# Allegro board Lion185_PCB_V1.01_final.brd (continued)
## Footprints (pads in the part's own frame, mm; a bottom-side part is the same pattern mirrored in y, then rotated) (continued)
CAE630W570HN
  rect 3.5x1.6 smd: 1(-2.85,0) 2(2.85,0)
CAE660W800HN
  rect 3.35x1.6 smd: 1(-2.45,0) 2(2.45,0)
CC0402N
  rect 0.55x0.5 smd: 1(-0.475,0) 2(0.475,0)
CC0603N
  rect 0.8x0.8 smd: 1(-0.75,0) 2(0.75,0)
CC0805N
  rect 1x1.2 smd: 1(-1,0) 2(1,0)
CC1206N
  rect 1.2x1.6 smd: 1(-1.6,0) 2(1.6,0)
CC1210N
  rect 1.3x2.6 smd: 1(-1.4,0) 2(1.4,0)
CCP7343N
  rect 2.6x2.6 smd: 1(-3.05,0) 2(3.05,0)
DOT
  round 0.508 smd: 1(0,0)
F1206N
  rect 1.3x1.8 smd: 1(-1.45,0) 2(1.45,0)
FB0603N
  rect 0.8x0.8 smd: 1(-0.75,0) 2(0.75,0)
FB0805N
  rect 1x1.2 smd: 1(-1,0) 2(1,0)
FB1206N
  rect 1.2x1.6 smd: 1(-1.6,0) 2(1.6,0)
FIL_175P200X120-4L
  rect 0.6x0.7 smd: 1(-0.5,0.875) 2(-0.5,-0.875) 3(0.5,-0.875) 4(0.5,0.875)
KPAK127P605-9N
  rect 0.9x1.5 smd: (-1.757,1.811)
  rect 0.7x0.5 smd: 1(-2.79,1.905) 3(2.79,-1.905) 4(2.79,-0.635) 5(2.79,0.635) 6(2.79,1.905)
  rect 1.85x3 smd: 2(-2.215,-0.637)
  rect 2.6x4.8 smd: 7(0.47,0.004)
LC3030DL
  rect 1.5x3.2 smd: 1(-1.05,0) 2(1.05,0)
LC4340N
  rect 2.5x1.5 smd: 1(0,1.85) 2(0,-1.85)
LC5757N
  rect 2.15x6.3 smd: 1(-2.075,0) 2(2.075,0)
LC6666N
  rect 2.3x3.3 smd: 1(-3.075,0) 2(3.075,0)
LC7266N
  rect 3.5x2.6 smd: 1(0,3.15) 2(0,-3.15)
LQFP40P1600X1600-128N
  oval 1.3x0.2 smd: 1(-7.65,6.2) 2(-7.65,5.8) 3(-7.65,5.4) 4(-7.65,5) 5(-7.65,4.6) 6(-7.65,4.2) 7(-7.65,3.8) 8(-7.65,3.4) 9(-7.65,3) 10(-7.65,2.6) 11(-7.65,2.2) 12(-7.65,1.8) 13(-7.65,1.4) 14(-7.65,1) 15(-7.65,0.6) 16(-7.65,0.2) 17(-7.65,-0.2) 18(-7.65,-0.6) 19(-7.65,-1) 20(-7.65,-1.4) 21(-7.65,-1.8) 22(-7.65,-2.2) 23(-7.65,-2.6) 24(-7.65,-3) 25(-7.65,-3.4) 26(-7.65,-3.8) 27(-7.65,-4.2) 28(-7.65,-4.6) 29(-7.65,-5) 30(-7.65,-5.4) 31(-7.65,-5.8) 32(-7.65,-6.2) 65(7.65,-6.2) 66(7.65,-5.8) 67(7.65,-5.4) 68(7.65,-5) 69(7.65,-4.6) 70(7.65,-4.2) 71(7.65,-3.8) 72(7.65,-3.4) 73(7.65,-3) 74(7.65,-2.6) 75(7.65,-2.2) 76(7.65,-1.8) 77(7.65,-1.4) 78(7.65,-1) 79(7.65,-0.6) 80(7.65,-0.2) 81(7.65,0.2) 82(7.65,0.6) 83(7.65,1) 84(7.65,1.4) 85(7.65,1.8) 86(7.65,2.2) 87(7.65,2.6) 88(7.65,3) 89(7.65,3.4) 90(7.65,3.8) 91(7.65,4.2) 92(7.65,4.6) 93(7.65,5) 94(7.65,5.4) 95(7.65,5.8) 96(7.65,6.2)
  oval 0.2x1.3 smd: 33(-6.2,-7.65) 34(-5.8,-7.65) 35(-5.4,-7.65) 36(-5,-7.65) 37(-4.6,-7.65) 38(-4.2,-7.65) 39(-3.8,-7.65) 40(-3.4,-7.65) 41(-3,-7.65) 42(-2.6,-7.65) 43(-2.2,-7.65) 44(-1.8,-7.65) 45(-1.4,-7.65) 46(-1,-7.65) 47(-0.6,-7.65) 48(-0.2,-7.65) 49(0.2,-7.65) 50(0.6,-7.65) 51(1,-7.65) 52(1.4,-7.65) 53(1.8,-7.65) 54(2.2,-7.65) 55(2.6,-7.65) 56(3,-7.65) 57(3.4,-7.65) 58(3.8,-7.65) 59(4.2,-7.65) 60(4.6,-7.65) 61(5,-7.65) 62(5.4,-7.65) 63(5.8,-7.65) 64(6.2,-7.65) 97(6.2,7.65) 98(5.8,7.65) 99(5.4,7.65) 100(5,7.65) 101(4.6,7.65) 102(4.2,7.65) 103(3.8,7.65) 104(3.4,7.65) 105(3,7.65) 106(2.6,7.65) 107(2.2,7.65) 108(1.8,7.65) 109(1.4,7.65) 110(1,7.65) 111(0.6,7.65) 112(0.2,7.65) 113(-0.2,7.65) 114(-0.6,7.65) 115(-1,7.65) 116(-1.4,7.65) 117(-1.8,7.65) 118(-2.2,7.65) 119(-2.6,7.65) 120(-3,7.65) 121(-3.4,7.65) 122(-3.8,7.65) 123(-4.2,7.65) 124(-4.6,7.65) 125(-5,7.65) 126(-5.4,7.65) 127(-5.8,7.65) 128(-6.2,7.65)
MARK-D100D250
  round 1 smd: 1(0,0)
MTG340H600
  round 6 hole 3.4: 1(0,0)
MTG340R580
  rect 5.8x5.8 hole 3.4: 1(0,0)
MTG380H500
  round 5 hole 3.8: 1(0,0)
MTG400H600
  round 6 hole 4: 1(0,0)
OSC120P150X670-4L
  rect 0.6x0.9 smd: 1(-0.6,3.3) 2(-0.6,-3.3) 3(0.6,-3.3) 4(0.6,3.3)
OSC127P200X600-2L
  rect 0.6x2.5 smd: 1(-0.6,4.98) 2(0.6,4.98)
OSC170P320X250-4N
  rect 1.4x1.15 smd: 1(-1.1,-0.85) 2(1.1,-0.85) 3(1.1,0.85) 4(-1.1,0.85)
PQFP50P365X365-14N
  oval 0.7x0.28 smd: 1(-1.775,-0.75) 7(1.775,-0.75) 8(1.775,0.75) 14(-1.775,0.75)
  oval 0.28x0.7 smd: 2(-1,-1.775) 3(-0.5,-1.775) 4(0,-1.775) 5(0.5,-1.775) 6(1,-1.775) 9(1,1.775) 10(0.5,1.775) 11(0,1.775) 12(-0.5,1.775) 13(-1,1.775)
  rect 2.05x2.05 smd: E1(0,0)
PVQFN50P480X480-24N
  oval 0.7x0.28 smd: 1(-2.025,1.25) 2(-2.025,0.75) 3(-2.025,0.25) 4(-2.025,-0.25) 5(-2.025,-0.75) 6(-2.025,-1.25) 13(2.025,-1.25) 14(2.025,-0.75) 15(2.025,-0.25) 16(2.025,0.25) 17(2.025,0.75) 18(2.025,1.25)
  oval 0.28x0.7 smd: 7(-1.25,-2.025) 8(-0.75,-2.025) 9(-0.25,-2.025) 10(0.25,-2.025) 11(0.75,-2.025) 12(1.25,-2.025) 19(1.25,2.025) 20(0.75,2.025) 21(0.25,2.025) 22(-0.25,2.025) 23(-0.75,2.025) 24(-1.25,2.025)
  rect 2.45x2.45 smd: E1(0,0)
QFN40P300X300-20N
  oval 0.6x0.2 smd: 1(-1.4,0.8) 2(-1.4,0.4) 3(-1.4,0) 4(-1.4,-0.4) 5(-1.4,-0.8) 11(1.4,-0.8) 12(1.4,-0.4) 13(1.4,0) 14(1.4,0.4) 15(1.4,0.8)
  oval 0.2x0.6 smd: 6(-0.8,-1.4) 7(-0.4,-1.4) 8(0,-1.4) 9(0.4,-1.4) 10(0.8,-1.4) 16(0.8,1.4) 17(0.4,1.4) 18(0,1.4) 19(-0.4,1.4) 20(-0.8,1.4)
  rect 1.8x1.8 smd: E1(0,0)
QFN40P600X600-48AN
  oval 0.7x0.2 smd: 1(-2.9,2.2) 2(-2.9,1.8) 3(-2.9,1.4) 4(-2.9,1) 5(-2.9,0.6) 6(-2.9,0.2) 7(-2.9,-0.2) 8(-2.9,-0.6) 9(-2.9,-1) 10(-2.9,-1.4) 11(-2.9,-1.8) 12(-2.9,-2.2) 25(2.9,-2.2) 26(2.9,-1.8) 27(2.9,-1.4) 28(2.9,-1) 29(2.9,-0.6) 30(2.9,-0.2) 31(2.9,0.2) 32(2.9,0.6) 33(2.9,1) 34(2.9,1.4) 35(2.9,1.8) 36(2.9,2.2)
  oval 0.2x0.7 smd: 13(-2.2,-2.9) 14(-1.8,-2.9) 15(-1.4,-2.9) 16(-1,-2.9) 17(-0.6,-2.9) 18(-0.2,-2.9) 19(0.2,-2.9) 20(0.6,-2.9) 21(1,-2.9) 22(1.4,-2.9) 23(1.8,-2.9) 24(2.2,-2.9) 37(2.2,2.9) 38(1.8,2.9) 39(1.4,2.9) 40(1,2.9) 41(0.6,2.9) 42(0.2,2.9) 43(-0.2,2.9) 44(-0.6,2.9) 45(-1,2.9) 46(-1.4,2.9) 47(-1.8,2.9) 48(-2.2,2.9)
  rect 3.6x4.05 smd: E1(0,0)
QFN40P600X600-48N
  oval 0.7x0.2 smd: 1(-2.9,2.2) 2(-2.9,1.8) 3(-2.9,1.4) 4(-2.9,1) 5(-2.9,0.6) 6(-2.9,0.2) 7(-2.9,-0.2) 8(-2.9,-0.6) 9(-2.9,-1) 10(-2.9,-1.4) 11(-2.9,-1.8) 12(-2.9,-2.2) 25(2.9,-2.2) 26(2.9,-1.8) 27(2.9,-1.4) 28(2.9,-1) 29(2.9,-0.6) 30(2.9,-0.2) 31(2.9,0.2) 32(2.9,0.6) 33(2.9,1) 34(2.9,1.4) 35(2.9,1.8) 36(2.9,2.2)
  oval 0.2x0.7 smd: 13(-2.2,-2.9) 14(-1.8,-2.9) 15(-1.4,-2.9) 16(-1,-2.9) 17(-0.6,-2.9) 18(-0.2,-2.9) 19(0.2,-2.9) 20(0.6,-2.9) 21(1,-2.9) 22(1.4,-2.9) 23(1.8,-2.9) 24(2.2,-2.9) 37(2.2,2.9) 38(1.8,2.9) 39(1.4,2.9) 40(1,2.9) 41(0.6,2.9) 42(0.2,2.9) 43(-0.2,2.9) 44(-0.6,2.9) 45(-1,2.9) 46(-1.4,2.9) 47(-1.8,2.9) 48(-2.2,2.9)
  rect 4.3x4.3 smd: E1(0,0)
QFN40P700X700-56AN
  oval 0.7x0.2 smd: 1(-3.4,2.6) 2(-3.4,2.2) 3(-3.4,1.8) 4(-3.4,1.4) 5(-3.4,1) 6(-3.4,0.6) 7(-3.4,0.2) 8(-3.4,-0.2) 9(-3.4,-0.6) 10(-3.4,-1) 11(-3.4,-1.4) 12(-3.4,-1.8) 13(-3.4,-2.2) 14(-3.4,-2.6) 29(3.4,-2.6) 30(3.4,-2.2) 31(3.4,-1.8) 32(3.4,-1.4) 33(3.4,-1) 34(3.4,-0.6) 35(3.4,-0.2) 36(3.4,0.2) 37(3.4,0.6) 38(3.4,1) 39(3.4,1.4) 40(3.4,1.8) 41(3.4,2.2) 42(3.4,2.6)
  oval 0.2x0.7 smd: 15(-2.6,-3.4) 16(-2.2,-3.4) 17(-1.8,-3.4) 18(-1.4,-3.4) 19(-1,-3.4) 20(-0.6,-3.4) 21(-0.2,-3.4) 22(0.2,-3.4) 23(0.6,-3.4) 24(1,-3.4) 25(1.4,-3.4) 26(1.8,-3.4) 27(2.2,-3.4) 28(2.6,-3.4) 43(2.6,3.4) 44(2.2,3.4) 45(1.8,3.4) 46(1.4,3.4) 47(1,3.4) 48(0.6,3.4) 49(0.2,3.4) 50(-0.2,3.4) 51(-0.6,3.4) 52(-1,3.4) 53(-1.4,3.4) 54(-1.8,3.4) 55(-2.2,3.4) 56(-2.6,3.4)
  rect 4.1x4.8 smd: E1(0,0)
QFN50P400X400-24AN
  oval 0.8x0.28 smd: 1(-2,1.25) 2(-2,0.75) 3(-2,0.25) 4(-2,-0.25) 5(-2,-0.75) 6(-2,-1.25) 13(2,-1.25) 14(2,-0.75) 15(2,-0.25) 16(2,0.25) 17(2,0.75) 18(2,1.25)
  oval 0.28x0.8 smd: 7(-1.25,-2) 8(-0.75,-2) 9(-0.25,-2) 10(0.25,-2) 11(0.75,-2) 12(1.25,-2) 19(1.25,2) 20(0.75,2) 21(0.25,2) 22(-0.25,2) 23(-0.75,2) 24(-1.25,2)
  rect 2.25x2.25 smd: E1(0,0)
QFN50P400X400-24BN
  oval 0.8x0.28 smd: 1(-2,1.25) 2(-2,0.75) 3(-2,0.25) 4(-2,-0.25) 5(-2,-0.75) 6(-2,-1.25) 13(2,-1.25) 14(2,-0.75) 15(2,-0.25) 16(2,0.25) 17(2,0.75) 18(2,1.25)
  oval 0.28x0.8 smd: 7(-1.25,-2) 8(-0.75,-2) 9(-0.25,-2) 10(0.25,-2) 11(0.75,-2) 12(1.25,-2) 19(1.25,2) 20(0.75,2) 21(0.25,2) 22(-0.25,2) 23(-0.75,2) 24(-1.25,2)
  rect 2.5x2.5 smd: E1(0,0)
RC0402N
  rect 0.55x0.5 smd: 1(-0.475,0) 2(0.475,0)
RC0603N
  rect 0.8x0.8 smd: 1(-0.75,0) 2(0.75,0)
RC0805N
  rect 1x1.2 smd: 1(-1,0) 2(1,0)
RC1206N
  rect 1.2x1.6 smd: 1(-1.6,0) 2(1.6,0)
RC2512N
  rect 1.65x3.68 smd: 1(-2.855,0) 2(2.855,0)
S0N50P250X650-15N
  oval 1.25x0.28 smd: 1(-0.875,2.75) 2(-0.875,2.25) 3(-0.875,1.75) 4(-0.875,1.25) 5(-0.875,0.75) 6(-0.875,0.25) 7(-0.875,-0.25) 8(-0.875,-0.75) 9(-0.875,-1.25) 10(-0.875,-1.75) 11(-0.875,-2.25) 12(-0.875,-2.75) 13(0.875,-1.5) 14(0.875,0) 15(0.875,1.5)
SMD-CN-50P-6N-H
  oval 0.28x1.25 smd: 1(-1.5,2.325) 2(-1,2.325) 3(-0.5,2.325) 4(0,2.325) 5(0.5,2.325) 6(1,2.325)
  rect 2x3 smd: E1(-3.19,0) E2(2.69,0)
SMD-CN-50P-20N-H
  oval 0.28x1.25 smd: 1(-4.75,2.325) 2(-4.25,2.325) 3(-3.75,2.325) 4(-3.25,2.325) 5(-2.75,2.325) 6(-2.25,2.325) 7(-1.75,2.325) 8(-1.25,2.325) 9(-0.75,2.325) 10(-0.25,2.325) 11(0.25,2.325) 12(0.75,2.325) 13(1.25,2.325) 14(1.75,2.325) 15(2.25,2.325) 16(2.75,2.325) 17(3.25,2.325) 18(3.75,2.325) 19(4.25,2.325) 20(4.75,2.325)
  rect 2x3.4 smd: E1(-6.44,0.4) E2(6.44,0.4)
SMD-CN-80P-2N
  rect 0.5x1 smd: 1(-0.4,0) 2(0.4,0)
  rect 1.2x1.7 smd: E1(-1.7,-1.95) E2(1.7,-1.95)
SMD-CN-100P-4BN
  rect 0.6x1.55 smd: 1(-1.5,3.875) 2(-0.5,3.875) 3(0.5,3.875) 4(1.5,3.875)
  rect 1.2x1.8 smd: E1(-2.8,0) E2(2.8,0)
SMD-CN-100P-5L
  rect 0.6x1.55 smd: 1(-2,3.875) 2(-1,3.875) 3(0,3.875) 4(1,3.875) 5(2,3.875)
  rect 1.2x1.8 smd: E1(-3.3,0) E2(3.3,0)
SMD-CN-100P-6L
  rect 0.6x1.55 smd: 1(-2.5,3.875) 2(-1.5,3.875) 3(-0.5,3.875) 4(0.5,3.875) 5(1.5,3.875) 6(2.5,3.875)
  rect 1.2x1.8 smd: E1(-3.8,0) E2(3.8,0)
SMD-CN-100P-10L
  rect 0.6x1.55 smd: 1(-4.5,0) 2(-3.5,0) 3(-2.5,0) 4(-1.5,0) 5(-0.5,0) 6(0.5,0) 7(1.5,0) 8(2.5,0) 9(3.5,0) 10(4.5,0)
  rect 1x2 smd: E1(-5.55,-3.775) E2(5.55,-3.775)
SMD-CN-100P-20L
  rect 0.6x1.55 smd: 1(-9.5,3.875) 2(-8.5,3.875) 3(-7.5,3.875) 4(-6.5,3.875) 5(-5.5,3.875) 6(-4.5,3.875) 7(-3.5,3.875) 8(-2.5,3.875) 9(-1.5,3.875) 10(-0.5,3.875) 11(0.5,3.875) 12(1.5,3.875) 13(2.5,3.875) 14(3.5,3.875) 15(4.5,3.875) 16(5.5,3.875) 17(6.5,3.875) 18(7.5,3.875) 19(8.5,3.875) 20(9.5,3.875)
  rect 1.2x1.8 smd: E1(-10.8,0) E2(10.8,0)
SMD-CN-125P-2WBN
  rect 0.8x1.5 smd: 1(-0.625,2.49) 2(0.625,2.49)
  rect 2x2.5 smd: E1(-3.175,0) E2(3.175,0)
SMD-CN-125P-4N-JS
  rect 0.8x1.5 smd: 1(-1.875,2.5) 2(-0.625,2.5) 3(0.625,2.5) 4(1.875,2.5)
  rect 2x2.5 smd: E1(-4.425,0) E2(4.425,0)
SMD-CN-CARD-75P-22N
  round 1.6 hole 1.6 unplated: (-9,0) (9,0)
  rect 0.45x2.2 smd: CD(-12.24,5.4) M1(-5.52,5.4) M2(-4.02,5.4) M3(-2.52,5.4) M4(-1.02,5.4) M5(0.48,5.4) M6(1.98,5.4) M7(3.48,5.4) M8(4.98,5.4) M9(6.48,5.4) M10(7.98,5.4) S1(7.23,5.4) S2(4.23,5.4) S3(1.23,5.4) S4(-0.27,5.4) S5(-3.27,5.4) S6(-6.27,5.4) S7(-8.05,5.4) S8(-9.75,5.4) S9(9.38,5.4) WP1(-11.12,5.4) WP2(-7.12,5.4)
  rect 1.5x2.8 smd: E1(-13.6,1) E2(-13.6,-17) E3(13.6,-17) E4(13.6,1)
SMD-DDR-60X1020P-204N-R
  round 1.1 hole 1.1 unplated: (-33.4,0)
  round 1.6 hole 1.6 unplated: (33.4,0)
  rect 0.35x2 smd: 1(31.65,4.1) 2(31.35,-4.1) 3(31.05,4.1) 4(30.75,-4.1) 5(30.45,4.1) 6(30.15,-4.1) 7(29.85,4.1) 8(29.55,-4.1) 9(29.25,4.1) 10(28.95,-4.1) 11(28.65,4.1) 12(28.35,-4.1) 13(28.05,4.1) 14(27.75,-4.1) 15(27.45,4.1) 16(27.15,-4.1) 17(26.85,4.1) 18(26.55,-4.1) 19(26.25,4.1) 20(25.95,-4.1) 21(25.65,4.1) 22(25.35,-4.1) 23(25.05,4.1) 24(24.75,-4.1) 25(24.45,4.1) 26(24.15,-4.1) 27(23.85,4.1) 28(23.55,-4.1) 29(23.25,4.1) 30(22.95,-4.1) 31(22.65,4.1) 32(22.35,-4.1) 33(22.05,4.1) 34(21.75,-4.1) 35(21.45,4.1) 36(21.15,-4.1) 37(20.85,4.1) 38(20.55,-4.1) 39(20.25,4.1) 40(19.95,-4.1) 41(19.65,4.1) 42(19.35,-4.1) 43(19.05,4.1) 44(18.75,-4.1) 45(18.45,4.1) 46(18.15,-4.1) 47(17.85,4.1) 48(17.55,-4.1) 49(17.25,4.1) 50(16.95,-4.1) 51(16.65,4.1) 52(16.35,-4.1) 53(16.05,4.1) 54(15.75,-4.1) 55(15.45,4.1) 56(15.15,-4.1) 57(14.85,4.1) 58(14.55,-4.1) 59(14.25,4.1) 60(13.95,-4.1) 61(13.65,4.1) 62(13.35,-4.1) 63(13.05,4.1) 64(12.75,-4.1) 65(12.45,4.1) 66(12.15,-4.1) 67(11.85,4.1) 68(11.55,-4.1) 69(11.25,4.1) 70(10.95,-4.1) 71(10.65,4.1) 72(10.35,-4.1) 73(7.65,4.1) 74(7.35,-4.1) 75(7.05,4.1) 76(6.75,-4.1) 77(6.45,4.1) 78(6.15,-4.1) 79(5.85,4.1) 80(5.55,-4.1) 81(5.25,4.1) 82(4.95,-4.1) 83(4.65,4.1) 84(4.35,-4.1) 85(4.05,4.1) 86(3.75,-4.1) 87(3.45,4.1) 88(3.15,-4.1) 89(2.85,4.1) 90(2.55,-4.1) 91(2.25,4.1) 92(1.95,-4.1) 93(1.65,4.1) 94(1.35,-4.1) 95(1.05,4.1) 96(0.75,-4.1) 97(0.45,4.1) 98(0.15,-4.1) 99(-0.15,4.1) 100(-0.45,-4.1) 101(-0.75,4.1) 102(-1.05,-4.1) 103(-1.35,4.1) 104(-1.65,-4.1) 105(-1.95,4.1) 106(-2.25,-4.1) 107(-2.55,4.1) 108(-2.85,-4.1) 109(-3.15,4.1) 110(-3.45,-4.1) 111(-3.75,4.1) 112(-4.05,-4.1) 113(-4.35,4.1) 114(-4.65,-4.1) 115(-4.95,4.1) 116(-5.25,-4.1) 117(-5.55,4.1) 118(-5.85,-4.1) 119(-6.15,4.1) 120(-6.45,-4.1) 121(-6.75,4.1) 122(-7.05,-4.1) 123(-7.35,4.1) 124(-7.65,-4.1) 125(-7.95,4.1) 126(-8.25,-4.1) 127(-8.55,4.1) 128(-8.85,-4.1) 129(-9.15,4.1) 130(-9.45,-4.1) 131(-9.75,4.1) 132(-10.05,-4.1) 133(-10.35,4.1) 134(-10.65,-4.1) 135(-10.95,4.1) 136(-11.25,-4.1) 137(-11.55,4.1) 138(-11.85,-4.1) 139(-12.15,4.1) 140(-12.45,-4.1) 141(-12.75,4.1) 142(-13.05,-4.1) 143(-13.35,4.1) 144(-13.65,-4.1) 145(-13.95,4.1) 146(-14.25,-4.1) 147(-14.55,4.1) 148(-14.85,-4.1) 149(-15.15,4.1) 150(-15.45,-4.1) 151(-15.75,4.1) 152(-16.05,-4.1) 153(-16.35,4.1) 154(-16.65,-4.1) 155(-16.95,4.1) 156(-17.25,-4.1) 157(-17.55,4.1) 158(-17.85,-4.1) 159(-18.15,4.1) 160(-18.45,-4.1) 161(-18.75,4.1) 162(-19.05,-4.1) 163(-19.35,4.1) 164(-19.65,-4.1) 165(-19.95,4.1) 166(-20.25,-4.1) 167(-20.55,4.1) 168(-20.85,-4.1) 169(-21.15,4.1) 170(-21.45,-4.1) 171(-21.75,4.1) 172(-22.05,-4.1) 173(-22.35,4.1) 174(-22.65,-4.1) 175(-22.95,4.1) 176(-23.25,-4.1) 177(-23.55,4.1) 178(-23.85,-4.1) 179(-24.15,4.1) 180(-24.45,-4.1) 181(-24.75,4.1) 182(-25.05,-4.1) 183(-25.35,4.1) 184(-25.65,-4.1) 185(-25.95,4.1) 186(-26.25,-4.1) 187(-26.55,4.1) 188(-26.85,-4.1) 189(-27.15,4.1) 190(-27.45,-4.1) 191(-27.75,4.1) 192(-28.05,-4.1) 193(-28.35,4.1) 194(-28.65,-4.1) 195(-28.95,4.1) 196(-29.25,-4.1) 197(-29.55,4.1) 198(-29.85,-4.1) 199(-30.15,4.1) 200(-30.45,-4.1) 201(-30.75,4.1) 202(-31.05,-4.1) 203(-31.35,4.1) 204(-31.65,-4.1)
  rect 3.6x4.6 smd: E1(-32.8,-12) E2(32.8,-12)
SMD-FPC-50P-6N-OR
  rect 0.3x0.8 smd: 1(1.25,2.87) 2(0.75,2.87) 3(0.25,2.87) 4(-0.25,2.87) 5(-0.75,2.87) 6(-1.25,2.87)
  rect 0.4x0.8 smd: E1(-2.25,0.37) E2(2.25,0.37)
SMD-FPC-50P-14N
  rect 0.3x1.25 smd: 1(-3.5,2.075) 2(-3,2.075) 3(-2.5,2.075) 4(-2,2.075) 5(-1.5,2.075) 6(-1,2.075) 7(-0.5,2.075) 8(0,2.075) 9(0.5,2.075) 10(1,2.075) 11(1.5,2.075) 12(2,2.075) 13(2.5,2.075) 14(3,2.075)
  rect 2x3 smd: E1(-5.19,-0.25) E2(4.69,-0.25)
SMD-FPC-100P-4N-JS
  rect 0.6x2 smd: 1(-1.5,1.9) 2(-0.5,1.9) 3(0.5,1.9) 4(1.5,1.9)
  rect 2.6x2.2 smd: E1(-4.1,-0.202) E2(4.1,-0.202)
SMD-HDMI-CN-50P-19AN
  oval 0.28x1.9 smd: 1(4.75,1) 2(4.25,1) 3(3.75,1) 4(3.25,1) 5(2.75,1) 6(2.25,1) 7(1.75,1) 8(1.25,1) 9(0.75,1) 10(0.25,1) 11(-0.25,1) 12(-0.75,1) 13(-1.25,1) 14(-1.75,1) 15(-2.25,1) 16(-2.75,1) 17(-3.25,1) 18(-3.75,1) 19(-4.25,1)
  round 1.7 hole 1.3: E1(-7.25,0) E2(7.25,0) E3(7.25,-4.9) E4(-7.25,-4.9)
SMD-PCIE-80X820P-52BN-L
  round 1.6 hole 1.6 unplated: (-12.5,0)
  round 1.1 hole 1.1 unplated: (12.5,0)
  rect 0.6x2 smd: 1(-11.8,-4.1) 2(-11.4,4.1) 3(-11,-4.1) 4(-10.6,4.1) 5(-10.2,-4.1) 6(-9.8,4.1) 7(-9.4,-4.1) 8(-9,4.1) 9(-8.6,-4.1) 10(-8.2,4.1) 11(-7.8,-4.1) 12(-7.4,4.1) 13(-7,-4.1) 14(-6.6,4.1) 15(-6.2,-4.1) 16(-5.8,4.1) 17(-2.2,-4.1) 18(-1.8,4.1) 19(-1.4,-4.1) 20(-1,4.1) 21(-0.6,-4.1) 22(-0.2,4.1) 23(0.2,-4.1) 24(0.6,4.1) 25(1,-4.1) 26(1.4,4.1) 27(1.8,-4.1) 28(2.2,4.1) 29(2.6,-4.1) 30(3,4.1) 31(3.4,-4.1) 32(3.8,4.1) 33(4.2,-4.1) 34(4.6,4.1) 35(5,-4.1) 36(5.4,4.1) 37(5.8,-4.1) 38(6.2,4.1) 39(6.6,-4.1) 40(7,4.1) 41(7.4,-4.1) 42(7.8,4.1) 43(8.2,-4.1) 44(8.6,4.1) 45(9,-4.1) 46(9.4,4.1) 47(9.8,-4.1) 48(10.2,4.1) 49(10.6,-4.1) 50(11,4.1) 51(11.4,-4.1) 52(11.8,4.1)
  rect 2.3x3.2 smd: E1(-14.65,-3.5) E2(14.65,-3.5)
  round 5.994 hole 3.607: E3(12.1,23.9)
SMD-TRANSF-127P-16N
  rect 1.9x0.8 smd: 1(-4.2,4.445) 2(-4.2,3.175) 3(-4.2,1.905) 4(-4.2,0.635) 5(-4.2,-0.635) 6(-4.2,-1.905) 7(-4.2,-3.175) 8(-4.2,-4.445) 9(4.2,-4.445) 10(4.2,-3.175) 11(4.2,-1.905) 12(4.2,-0.635) 13(4.2,0.635) 14(4.2,1.905) 15(4.2,3.175) 16(4.2,4.445)
SMD-USB-200X250P-4BN
  rect 1.3x2 smd: 1(3.5,0) 2(1,0) 3(-1,0) 4(-3.5,0)
  rect 2x2.6 smd: E1(-7.85,-11) E2(7.85,-11)
  oval 2.2x4.1 hole 0.7x2.4: E3(-6.4,-1.6) E4(6.4,-1.6)
SOD0806N
  rect 0.4x0.35 smd: N(-0.45,0) P(0.45,0)
SOD1713N
  rect 0.8x0.6 smd: N(1.25,0) P(-1.25,0)
SOD2514N
  rect 1.2x0.5 smd: N(-1.15,0) P(1.15,0)
SOD2818N
  rect 2.2x1.4 smd: N(1,0)
  rect 0.9x1.4 smd: P(-1.65,0)
SOD5227N
  rect 2x2 smd: N(-2.095,0) P(2.095,0)
SOD5336N
  rect 2.5x2.3 smd: N(2.15,0) P(-2.15,0)
SOIC127P600-8N
  rect 1.9x0.6 smd: 1(-2.55,1.905) 2(-2.55,0.635) 3(-2.55,-0.635) 4(-2.55,-1.905) 5(2.55,-1.905) 6(2.55,-0.635) 7(2.55,0.635) 8(2.55,1.905)
SOIC127P800-8N
  rect 1.8x0.6 smd: 1(-3.6,1.905) 2(-3.6,0.635) 3(-3.6,-0.635) 4(-3.6,-1.905) 5(3.6,-1.905) 6(3.6,-0.635) 7(3.6,0.635) 8(3.6,1.905)
SON35P100-8N
  oval 0.55x0.2 smd: 1(-0.46,0.525) 2(-0.46,0.174) 3(-0.46,-0.176) 4(-0.46,-0.526) 5(0.46,-0.526) 6(0.46,-0.176) 7(0.46,0.174) 8(0.46,0.525)
SON50P200X200-8N
  oval 0.6x0.25 smd: 1(-1,0.749) 2(-1,0.249) 3(-1,-0.251) 4(-1,-0.751) 5(1,-0.751) 6(1,-0.251) 7(1,0.249) 8(1,0.749)
  rect 0.9x1.6 smd: E1(0,0)
SON127P500X600-8AN
  oval 0.9x0.6 smd: 1(-2.85,1.905) 2(-2.85,0.635) 3(-2.85,-0.635) 4(-2.85,-1.905) 5(2.85,-1.905) 6(2.85,-0.635) 7(2.85,0.635) 8(2.85,1.905)
  rect 3.4x4 smd: E1(0,0)
SOP35P100-3N
  rect 0.3x0.3 smd: 1(-0.35,-0.425) 2(0.35,-0.425) 3(0,0.425)
SOT50P160-3N
  rect 0.8x0.6 smd: 1(-0.725,0.5) 2(-0.725,-0.5) 3(0.725,0)
SOT65P190-5N
  oval 1.1x0.35 smd: 1(-0.95,0.65) 2(-0.95,0) 3(-0.95,-0.65) 4(0.95,-0.65) 5(0.95,0.65)
SOT65P210-3N
  rect 1.2x0.45 smd: 1(-0.9,0.65) 2(-0.9,-0.65) 3(0.9,0)
SOT65P210-5N
  rect 1.1x0.4 smd: 1(-0.95,0.65) 2(-0.95,0) 3(-0.95,-0.65) 4(0.95,-0.65) 5(0.95,0.65)
SOT65P280-8N
  rect 1x0.35 smd: 1(-1.35,0.975) 2(-1.35,0.325) 3(-1.35,-0.325) 4(-1.35,-0.975) 5(1.35,-0.975) 6(1.35,-0.325) 7(1.35,0.325) 8(1.35,0.975)
SOT95P230-3N
  rect 1.25x0.6 smd: 1(-1.05,0.95) 2(-1.05,-0.95) 3(1.05,0)
SOT95P240-3BN
  rect 1.4x0.6 smd: 1(-1,0.95) 2(-1,-0.95) 3(1,0)
SOT95P240-3N
  rect 1.4x0.6 smd: 1(-1,0.95) 2(-1,-0.95) 3(1,0)
SOT95P280-3N
  rect 1.35x0.6 smd: 1(-1.25,0.95) 2(-1.25,-0.95) 3(1.25,0)
SOT95P280-5N
  rect 1.3x0.6 smd: 1(-1.25,0.95) 2(-1.25,0) 3(-1.25,-0.95) 4(1.25,-0.95) 5(1.25,0.95)
SOT95P280-6FN
  rect 1x0.6 smd: 1(-1.2,0.95) 2(-1.2,0) 3(-1.2,-0.95) 4(1.2,-0.95) 5(1.2,0) 6(1.2,0.95)
SOT229P990-3N
  rect 1x2.2 smd: 1(-2.29,-3.35) 2(2.29,-3.35)
  rect 5.5x5.3 smd: 3(0,3.15)
SSOP65P780-28N
  rect 1.4x0.3 smd: 1(-3.35,4.225) 2(-3.35,3.575) 3(-3.35,2.925) 4(-3.35,2.275) 5(-3.35,1.625) 6(-3.35,0.975) 7(-3.35,0.325) 8(-3.35,-0.325) 9(-3.35,-0.975) 10(-3.35,-1.625) 11(-3.35,-2.275) 12(-3.35,-2.925) 13(-3.35,-3.575) 14(-3.35,-4.225) 15(3.35,-4.225) 16(3.35,-3.575) 17(3.35,-2.925) 18(3.35,-2.275) 19(3.35,-1.625) 20(3.35,-0.975) 21(3.35,-0.325) 22(3.35,0.325) 23(3.35,0.975) 24(3.35,1.625) 25(3.35,2.275) 26(3.35,2.925) 27(3.35,3.575) 28(3.35,4.225)
SW_330X390P_4N
  rect 1x0.7 smd: 1(-1.95,1.65) 2(-1.95,-1.65) 3(1.95,1.65) 4(1.95,-1.65)
SW_TMG-53N
  rect 1.1x1.5 smd: 1(-1.85,3) 2(-1.85,-3) 3(1.85,3) 4(1.85,-3)
  rect 0.6x1.4 smd: 5(-2.5,0) 6(2.5,0)
TDFN50P300X300-10N
  oval 0.65x0.25 smd: 1(-1.325,1) 2(-1.325,0.5) 3(-1.325,0) 4(-1.325,-0.5) 5(-1.325,-1) 6(1.325,-1) 7(1.325,-0.5) 8(1.325,0) 9(1.325,0.5) 10(1.325,1)
  rect 1.5x2.5 smd: E1(0,0)
TEST80
  round 0.8 smd: 1(0,0)
TEST120
  round 1.2 smd: 1(0,0)
TH-CN-200P-2N-H
  round 1.4 hole 0.8: 1(-1,0) 2(1,0)
TH-CN-DCIN-530X740P-5N
  round 2.4 hole 2.4 unplated: (0,0)
  oval 1.4x3.1 hole 0.6x2.3: 1(-6.198,-0.999) 5(3.602,-0.999)
  oval 1.6x3 hole 0.8x2: 2(-5.3,6.401) 3(0,6.401) 4(3.2,6.401)
TH-EARPHONE-6BN
  round 1.2 hole 1.2 unplated: (-3,2.5) (3.5,2.5)
  oval 1.1x1.8 hole 0.5x1.2: 2(-1.6,-4.5) 3(3.2,-2.5) 4(4.5,-4.5) 5(-3.6,-1.5) 6(1.6,-4.5)
  oval 1.8x1.1 hole 1.2x0.5: 7(0,3.6)
  oval 1x1.5 hole 0.6x1.1: E1(-4.45,0.7) E2(4.85,0.7)
TH-RJ45-102X110P-8AN
  round 1.2 hole 0.9: 1(-3.57,12.41) 2(-2.55,11.31) 3(-1.53,12.41) 4(-0.51,11.31) 5(0.51,12.41) 6(1.53,11.31) 7(2.55,12.41) 8(3.57,11.31)
  oval 2.2x4.1 hole 0.7x2.6: E1(-8.04,3.91) E2(8.04,3.91)
TH-USB-200X150P-9GN
  round 1.2 hole 0.7: 1(3.5,1.65) 2(1,1.65) 3(-1,1.65) 4(-3.5,1.65) 5(-4,0.15) 6(-2,0.15) 7(0,0.15) 8(2,0.15) 9(4,0.15)
  oval 1.4x3.1 hole 0.6x2.3: E1(-6.4,-1.85) E2(6.4,-1.85)
TSOP65P490-8N
  rect 1.45x0.4 smd: 1(-2.2,0.975) 2(-2.2,0.325) 3(-2.2,-0.325) 4(-2.2,-0.975) 5(2.2,-0.975) 6(2.2,-0.325) 7(2.2,0.325) 8(2.2,0.975)
unnamed
  round 8 hole 8 unplated: (0,0)
UQFN40P200X170-12N
  oval 0.7x0.4 smd: 1(-0.7,0.9)
  oval 0.7x0.2 smd: 2(-0.7,0.401) 3(-0.7,0.002) 4(-0.7,-0.399) 5(-0.7,-0.799) 7(0.7,-0.799) 8(0.7,-0.399) 9(0.7,0.002) 10(0.7,0.401) 11(0.7,0.801)
  oval 0.2x0.7 smd: 6(0,-0.85) 12(0,0.85)
VSOP127P790-8N
  rect 1.6x0.6 smd: 1(-3.44,1.905) 2(-3.44,0.635) 3(-3.44,-0.635) 4(-3.44,-1.905) 5(3.44,-1.905) 6(3.44,-0.635) 7(3.44,0.635) 8(3.44,1.905)

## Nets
3.3V_IN: C581.2 FB14.1 FB15.2 R691.1 R694.2 R695.1 U77.24(V33)
3.3V_IN_1: C608.2 FB17.1 FB18.2 R736.1 R738.1 R741.2 U83.24(V33)
+V1.0A: C65.1 C68.1 C86.1 C87.1 C88.1 C408.2 C412.1 C415.2 C445.1 C554.1 CP11.1 L9.2 R293.1 R468.2 R571.2 U1.B6(UNCORE_V1P0_G3_B6) U1.C3(USB3_V1P0_G3_C3) U1.C5(UNCORE_V1P0_G3_C5) U1.U22(UNCORE_V1P0_G3_U22) U1.V22(UNCORE_V1P0_G3_V22) U1.Y19(USB3_V1P0_G3_Y19) U46.1(VIN1) U46.2(VIN2) U47.3(VOUT) U48.1(VIN1) U48.2(VIN2)
+V1.0S: C49.2 C55.2 C70.1 C72.2 C75.2 C83.1 C84.1 C85.1 C96.1 C403.2 C446.1 C518.1 R377.2 R516.1 R517.1 R518.1 R528.1 R580.1 R677.1 R678.1 U1.AF16(UNCORE_V1P0_S3_AF16) U1.AF18(UNCORE_V1P0_S3_AF18) U1.AK18(PCIE_V1P0_S3_AK18) U1.AM18(PCIE_V1P0_S3_AM18) U1.AM21(PCIE_V1P0_S3_AM21) U1.AN18(PCIE_GBE_SATA_V1P0_S3_AN18) U1.AN19(SATA_V1P0_S3_AN19) U1.AN21(PCIE_V1P0_S3_AN21) U1.AN25(GPIO_V1P0_S3_AN25) U1.BJ6(VGA_V1P0_S3_BJ6) U1.G1(UNCORE_V1P0_S3_G1) U1.M14(USB_V1P0_S3_M14) U1.U18(USB_V1P0_S3_U18) U1.U19(USB_V1P0_S3_U19) U1.V32(SVID_V1P0_S3_V32) U1.Y18(UNCORE_V1P0_S3_Y18) U46.7(VOUT2) U46.8(VOUT1)
+V1.0SX: C58.1 C60.1 C61.1 C62.1 C66.1 C67.1 C69.1 C76.1 C77.1 C78.1 C79.1 C80.1 C414.2 C555.1 R677.2 R678.2 R725.2 U1.AA36(DRAM_V1P0_S0IX_AA36) U1.AD35(DRAM_V1P0_S0IX_AD35) U1.AF21(UNCORE_V1P0_S0IX_AF21) U1.AF35(DRAM_V1P0_S0IX_AF35) U1.AF36(DRAM_V1P0_S0IX_AF36) U1.AG21(UNCORE_V1P0_S0IX_AG21) U1.AJ18(DDI_V1P0_S0IX_AJ18) U1.AJ36(DRAM_V1P0_S0IX_AJ36) U1.AK19(DDI_V1P0_S0IX_AK19) U1.AK21(DDI_V1P0_S0IX_AK21) U1.AK35(DRAM_V1P0_S0IX_AK35) U1.AK36(DRAM_V1P0_S0IX_AK36) U1.AM16(DDI_V1P0_S0IX_AM16) U1.AN29(VIS_V1P0_S0IX_AN29) U1.AN30(VIS_V1P0_S0IX_AN30) U1.V24(VIS_V1P0_S0IX_V24) U1.Y22(VIS_V1P0_S0IX_Y22) U1.Y24(VIS_V1P0_S0IX_Y24) U1.Y35(DRAM_V1P0_S0IX_Y35) U1.Y36(DRAM_V1P0_S0IX_Y36) U48.7(VOUT2) U48.8(VOUT1)
+V1.2A: C438.1 C439.2 C553.1 R494.1 R573.2 R671.1 U53.1(VOUT1) U53.2(VOUT2) U53.3(VOUT3) U54.1(VIN1) U54.2(VIN2)
+V1.2S: C434.2 C552.1 R114.2 R557.2 U54.7(VOUT2) U54.8(VOUT1)
+V1.5S: C229.2 C266.1 C267.2 C432.1 C433.1 CN12.6(+1.5V_1) CN12.28(+1.5V_2) CN12.48(+1.5V_3) R111.1 R240.2 R487.2 R565.2 U20.1(VIN1) U20.2(VIN2) U52.1(VOUT1) U52.2(VOUT2) U52.3(VOUT3)
+V1.05S: C81.1 C420.1 C421.1 C537.1 C563.1 R118.1 R473.1 R567.2 U1.AA33(CORE_V1P05_S3_AA33) U1.AF33(CORE_V1P05_S3_AF33) U1.AG33(CORE_V1P05_S3_AG33) U1.AG35(CORE_V1P05_S3_AG35) U1.U33(CORE_V1P05_S3_U33) U1.U35(CORE_V1P05_S3_U35) U1.V33(CORE_V1P05_S3_V33) U49.1(VOUT1) U49.2(VOUT2) U49.3(VOUT3)
+V1.5S_AUDIO: FB9.2 R240.1 R260.2 U20.7(VOUT2) U20.8(VOUT1)
+V1.8A: C17.2 C20.1 C71.1 C284.1 C286.1 C425.1 C426.1 C427.2 C430.1 C435.1 C437.1 C529.1 C550.1 C564.1 D31.P R62.2 R63.2 R76.2 R77.1 R79.2 R80.1 R82.1 R83.1 R89.2 R90.2 R110.1 R298.1 R313.1 R314.2 R326.2 R480.1 R572.2 R582.1 R583.1 R584.1 R602.1 R638.2 R731.1 U1.AA18(UNCORE_V1P8_G3_AA18) U5.1(VIN1) U5.2(VIN2) U6.1(VCCA) U26.1(VCCA) U27.1(VCCA) U50.1(VOUT1) U50.2(VOUT2) U50.3(VOUT3) U51.1(VIN1) U51.2(VIN2) U52.7(VIN1) U52.8(VIN2) U52.9(VIN3) U53.7(VIN1) U53.8(VIN2) U53.9(VIN3)
+V1.8A_SPI: C16.2 R71.2 R72.2 R77.2 U3.8(VCC) U5.7(VOUT2) U5.8(VOUT1) U75.8(VCC)
+V1.8A_SPI_KBC: C521.2 R339.2 U70.5(OUT)
+V1.8S: C51.1 C52.1 C53.1 C54.1 C302.1 C422.2 C551.1 C566.1 Q102.1(G) Q103.1(G) R11.2 R12.2 R13.1 R17.2 R31.2 R36.2 R39.2 R41.2 R42.2 R43.2 R51.2 R52.2 R57.2 R91.2 R106.1 R108.1 R109.1 R112.1 R117.2 R202.1 R203.1 R492.2 R650.2 R682.2 R700.2 U1.AM30(UNCORE_V1P8_S3_AM30) U1.AN32(UNCORE_V1P8_S3_AN32) U1.U38(UNCORE_V1P8_S3_U38) U51.7(VOUT2) U51.8(VOUT1) U65.1(VCCA) U74.1(VCCA)
+V1.35_CRT: C99.2 C100.1 R119.2 U1.BD1(VGA_V1P35_S3_F1_BD1)
+V1.35S: C97.1 C98.1 C396.2 C557.1 R119.1 R378.2 R452.1 R676.1 U1.AG18(ICLK_V1P35_S3_F2) U1.AJ19(ICLK_V1P35_S3_F1_AJ19) U45.7(VOUT2) U45.8(VOUT1)
+V3.3A: C21.1 C128.1 C188.1 C285.1 C287.1 C321.1 C324.1 C326.1 C329.1 C331.1 C332.1 C373.1 C374.1 C423.1 C424.1 C497.1 C505.1 C515.1 C538.1 C560.2 C561.1 C726.2 C767.1 CN5.1 CN5.2 CN34.5 CN34.6 CP6.1 CP7.1 D1.P L7.2 R34.2 R56.2 R81.1 R130.1 R132.2 R206.2 R212.2 R327.1 R338.1 R340.1 R357.1 R358.1 R376.2 R390.2 R424.2 R448.2 R454.1 R462.2 R469.2 R471.1 R474.1 R477.1 R483.1 R488.1 R495.1 R498.1 R500.2 R503.1 R504.1 R513.1 R531.1 R537.2 R556.1 R558.2 R570.2 R594.1 R595.2 R670.1 R695.2 R728.2 R738.2 U6.11(VCCB) U7.1(VDD) U16.1(VIN1) U16.2(VIN2) U26.11(VCCB) U27.11(VCCB) U34.5(VCC) U36.5(VCC) U37.5(VCC) U38.5(VCC) U39.5(VCC) U40.5(VCC) U42.7(VO2) U50.7(VIN1) U50.8(VIN2) U50.9(VIN3) U56.7(CCSP2) U58.5(VCC) U60.1(VIN1) U60.2(VIN2) U68.1(VIN1) U68.2(VIN2) U73.5(VIN) U79.8(+V)
+V3.3A_KBC: C281.2 C282.2 C507.2 C570.1 C571.2 C572.2 FB13.1 L16.2 L17.2 Q69.1(G) R290.1 R296.1 R297.1 R299.1 R300.1 R302.1 R315.1 R333.2 R334.2 R657.2 R670.2 R689.2 U28.26(VSTBY6) U28.50(VSTBY5) U28.92(VSTBY4) U28.114(VSTBY3) U28.121(VSTBY2) U28.127(VSTBY1(PLL)) U70.1(IN)
+V3.3A_RTC: C9.2 C597.2 D1.N D2.N R65.2 R68.1 R291.1 U1.P22(RTC_VCC_P22)
+V3.3A_SOC: C59.2 C63.2 C548.2 R357.2 U1.N18(USB_V3P3_G3_N18) U1.N22(PCU_V3P3_G3_N22) U1.P18(USB_V3P3_G3_P18) U73.1(VOUT)
+V3.3A_WIFI: C263.1 C264.2 C265.2 C268.2 C269.2 C270.2 C512.2 C516.1 CN12.2(+3.3V_1) CN12.24(+3.3V_AUX) CN12.39(RSVD6) CN12.41(RSVD7) CN12.52(+3.3V_2) Q66.1(G) R594.2 U60.7(VOUT2) U60.8(VOUT1)
+V3.3AVCC: C283.1 FB13.2 U28.74(AVCC)
+V3.3S: C101.2 C102.2 C238.2 C241.1 C262.2 C292.2 C498.2 C499.1 C506.1 C519.1 C567.1 CN3.199(VDDSPD) CN13.1 CN14.1 CN14.2 CN14.14 CN14.15 CN14.18 D6.2(X2) D7.P FB3.2 FB4.2 FB7.2 FB16.1 Q9.1(G) Q10.1(G) R20.1 R84.2 R116.2 R121.2 R133.1 R201.1 R207.1 R217.2 R243.2 R269.1 R270.1 R271.1 R304.2 R392.2 R437.1 R559.2 R579.1 R590.1 R625.2 R628.2 R630.1 R631.1 R637.1 R649.2 R661.1 R683.1 R684.1 R703.1 R710.1 R729.2 R730.2 R750.1 R762.2 U1.AN24(VGA_V3P3_S3_AN24) U14.13(VCC) U14.15(VCC1) U22.5(VIN) U24.5(VCC) U29.5(VCC) U63.5(VCC) U65.8(VCCB) U68.7(VOUT2) U68.8(VOUT1) U74.8(VCCB)
+V3.3S_AUDIO: C233.2 C234.2 FB7.1 FB8.2 FB10.1 R258.2 R685.1 U22.1(VOUT) U23.36(CPVDD)
+V5_AVDD: C239.2 C240.1 FB5.1 R267.2 R268.2 U21.1(VOUT) U23.26(AVDD1)
+V5_PVDD: C247.2 C248.1 C251.2 C252.1 FB6.1 U19.1(VOUT) U23.41(PVDD1) U23.46(PVDD2)
+V5A: C19.2 C134.2 C309.1 C320.1 C334.1 C336.1 C371.1 C372.1 C388.2 C401.2 C402.2 C410.2 C411.1 C417.2 C429.2 C431.1 C436.1 C441.2 C500.2 C501.2 C504.2 C510.2 C562.1 C565.1 CP4.1 CP5.1 D26.P F3.1 F4.1 F5.1 F6.1 L6.1 R366.1 R371.1 R375.1 R380.1 R423.1 R461.2 R514.2 R562.2 R569.2 R692.1 R693.2 R696.1 R721.1 R739.1 R742.2 U5.4(VBIAS) U8.4(VBIAS) U16.4(VBIAS) U31.5(VIN) U41.5(VIN) U42.24(V01) U43.12(V5IN) U44.4(VBIAS) U45.4(VBIAS) U46.4(VBIAS) U47.10(V5DRV) U48.4(VBIAS) U49.10(VCNTL) U50.10(VCNTL) U51.4(VBIAS) U52.10(VCNTL) U53.10(VCNTL) U54.4(VBIAS) U55.5(VIN) U59.5(VIN) U68.4(VBIAS) U69.1(VIN1) U69.2(VIN2) U69.4(VBIAS)
+V5S: C183.2 C222.2 C223.2 C224.1 C226.1 C299.1 C300.1 C502.2 C503.2 C513.2 C618.2 C619.1 CN24.11 CN24.12 CN24.13 CN24.14 CN26.11 CN26.12 CN26.13 CN26.14 F2.2 FB1.2 FB5.2 FB6.2 R134.1 R235.2 R236.2 R237.2 R310.1 R316.1 R384.1 R386.1 R391.2 R627.2 R660.2 R743.2 R761.2 U15.3(VIN) U19.5(VIN) U20.4(VBIAS) U21.5(VIN) U60.4(VBIAS) U69.7(VOUT2) U69.8(VOUT1) U84.5(VIN)
+V5S_CAM: C621.2 C622.2 J3.1 U84.1(VOUT)
+V5S_HDMI: C184.2 CN8.18 D5.N R204.1 R205.1 U15.2(VOUT)
+V15A: C379.1 D25.2(X2)
AGND: C230.2 C232.1 C239.1 C240.2 C243.1 C244.2 C246.1 C389.2 C390.2 C508.2 C509.2 C583.2 C584.2 CN21.1 CN21.E1 CN21.E2 FB11.2 J4.4 J4.7 J4.E1 J4.E2 J7.3 J7.7 J7.E1 J7.E2 Q97.2(S) R252.2 R711.2 R719.2 U23.25(AVSS1) U23.38(AVSS2)
AVDD2: C243.2 C244.1 FB8.1 FB9.1 U23.40(AVDD2)
AVDD33: C702.2 C703.1 FB20.1 U95.4(AVDD33)
AVDD33_REG: C197.2 C198.1 R211.1 U17.34(VDDREG) U17.35(VDDREGA)
GND: C1.2 C7.1 C8.1 C9.1 C10.2 C11.1 C12.1 C13.1 C14.1 C16.1 C17.1 C18.1 C19.1 C20.2 C21.2 C22.1 C23.1 C24.1 C25.1 C26.1 C27.1 C28.1 C29.1 C30.1 C31.1 C32.1 C33.1 C34.1 C35.1 C36.1 C37.1 C38.1 C39.2 C40.2 C41.1 C42.1 C43.1 C44.1 C45.1 C46.2 C47.2 C48.2 C49.1 C50.1 C51.2 C52.2 C53.2 C54.2 C55.1 C56.2 C57.2 C58.2 C59.1 C60.2 C61.2 C62.2 C63.1 C64.1 C65.2 C66.2 C67.2 C68.2 C69.2 C70.2 C71.2 C72.1 C73.2 C74.2 C75.1 C76.2 C77.2 C78.2 C79.2 C80.2 C81.2 C83.2 C84.2 C85.2 C86.2 C87.2 C88.2 C89.2 C90.2 C91.2 C92.2 C93.2 C94.2 C95.2 C96.2 C97.2 C98.2 C99.1 C100.2 C101.1 C102.1 C103.1 C104.1 C105.2 C106.1 C107.1 C108.1 C109.1 C110.1 C111.1 C112.1 C113.1 C114.1 C115.1 C116.1 C117.1 C118.1 C119.1 C120.1 C121.1 C122.1 C123.1 C124.1 C125.1 C126.1 C127.1 C128.2 C130.1 C131.1 C132.2 C133.2 C134.1 C135.1 C136.1 C137.2 C150.1 C151.1 C152.1 C160.1 C161.1 C162.1 C164.1 C166.2 C169.2 C171.1 C172.1 C183.1 C184.1 C185.1 C186.2 C187.2 C188.2 C190.2 C191.2 C192.2 C193.2 C194.2 C195.2 C196.2 C197.1 C198.2 C199.1 C200.2 C201.2 C202.2 C203.2 C204.2 C205.2 C206.2 C207.2 C210.1 C211.2 C222.1 C223.1 C224.2 C225.1 C226.2 C227.1 C228.1 C229.1 C231.2 C233.1 C234.1 C235.2 C238.1 C241.2 C242.1 C247.1 C248.2 C251.1 C252.2 C253.1 C254.2 C255.1 C256.1 C257.1 C259.1 C260.1 C261.1 C262.1 C263.2 C264.1 C265.1 C266.2 C267.1 C268.1 C269.1 C270.1 C275.2 C281.1 C282.1 C283.2 C284.2 C285.2 C286.2 C287.2 C288.1 C289.2 C290.2 C291.2 C292.1 C293.2 C294.2 C296.2 C298.2 C299.2 C300.2 C301.2 C302.2 C303.1 C304.2 C305.1 C309.2 C310.1 C311.1 C312.2 C313.2 C316.1 C317.2 C318.2 C319.1 C320.2 C321.2 C322.1 C323.2 C324.2 C325.2 C326.2 C327.1 C328.2 C329.2 C330.2 C331.2 C332.2 C333.1 C334.2 C335.1 C336.2 C337.2 C360.2 C361.2 C362.2 C363.1 C364.1 C365.2 C366.2 C367.2 C368.1 C371.2 C372.2 C373.2 C374.2 C375.2 C376.1 C379.2 C380.2 C381.2 C382.2 C383.2 C384.2 C385.1 C387.2 C388.1 C391.2 C392.1 C393.2 C394.1 C395.1 C396.1 C397.1 C398.1 C399.1 C400.1 C401.1 C402.1 C403.1 C405.1 C406.2 C407.2 C408.1 C409.1 C410.1 C411.2 C412.2 C413.2 C414.1 C415.1 C416.1 C417.1 C418.2 C419.2 C420.2 C421.2 C422.1 C423.2 C424.2 C425.2 C426.2 C427.1 C428.1 C429.1 C430.2 C431.2 C432.2 C433.2 C434.1 C435.2 C436.2 C437.2 C438.2 C439.1 C440.1 C441.1 C442.1 C443.2 C444.2 C445.2 C446.2 C447.1 C448.2 C450.2 C451.2 C452.2 C453.2 C454.2 C455.2 C456.2 C457.2 C458.2 C459.2 C460.2 C465.1 C466.1 C467.1 C469.2 C470.2 C471.2 C472.2 C473.1 C475.2 C479.1 C481.2 C482.2 C483.2 C484.1 C485.2 C486.2 C487.2 C488.2 C489.2 C490.2 C491.2 C492.2 C493.2 C494.1 C495.1 C496.1 C497.2 C498.1 C499.2 C500.1 C501.1 C502.1 C503.1 C504.1 C505.2 C506.2 C507.1 C510.1 C511.1 C512.1 C513.1 C514.1 C515.2 C516.2 C518.2 C519.2 C521.1 C527.1 C529.2 C535.1 C536.2 C537.2 C538.2 C539.2 C540.2 C542.2 C543.2 C544.2 C545.2 C546.2 C547.2 C548.1 C549.1 C550.2 C551.2 C552.2 C553.2 C554.2 C555.2 C556.2 C557.2 C558.2 C559.2 C560.1 C561.2 C562.2 C565.2 C566.2 C567.2 C568.2 C571.1 C572.1 C573.1 C574.1 C575.1 C576.1 C577.1 C578.1 C579.1 C580.1 C581.1 C582.1 C586.1 C587.1 C596.1 C597.1 C598.2 C599.1 C600.1 C601.2 C602.1 C603.2 C604.2 C605.1 C606.1 C607.1 C608.1 C609.1 C610.1 C611.1 C612.1 C613.1 C614.1 C615.1 C616.1 C617.1 C618.1 C619.2 C620.1 C621.1 C622.1 C700.2 C701.2 C702.1 C703.2 C704.2 C705.2 C706.1 C707.2 C708.2 C709.2 C710.1 C726.1 C727.1 C764.1 C765.1 C766.2 C767.2 C845.1 C942.1 C992.1 CN2.2 CN2.E1 CN2.E2 CN3.2(VSS1) CN3.3(VSS2) CN3.8(VSS3) CN3.9(VSS4) CN3.13(VSS5) CN3.14(VSS6) CN3.19(VSS7) CN3.20(VSS8) CN3.25(VSS9) CN3.26(VSS10) CN3.31(VSS11) CN3.32(VSS12) CN3.37(VSS13) CN3.38(VSS14) CN3.43(VSS15) CN3.44(VSS16) CN3.48(VSS17) CN3.49(VSS18) CN3.54(VSS19) CN3.55(VSS20) CN3.60(VSS21) CN3.61(VSS22) CN3.65(VSS23) CN3.66(VSS24) CN3.71(VSS25) CN3.72(VSS26) CN3.127(VSS27) CN3.128(VSS28) CN3.133(VSS29) CN3.134(VSS30) CN3.138(VSS31) CN3.139(VSS32) CN3.144(VSS33) CN3.145(VSS34) CN3.150(VSS35) CN3.151(VSS36) CN3.155(VSS37) CN3.156(VSS38) CN3.161(VSS39) CN3.162(VSS40) CN3.167(VSS41) CN3.168(VSS42) CN3.172(VSS43) CN3.173(VSS44) CN3.178(VSS45) CN3.179(VSS46) CN3.184(VSS47) CN3.185(VSS48) CN3.189(VSS49) CN3.190(VSS50) CN3.195(VSS51) CN3.196(VSS52) CN3.E1 CN3.E2 CN4.4 CN4.E1 CN4.E2 CN5.3 CN5.5 CN5.E1 CN5.E2 CN8.2 CN8.5 CN8.8 CN8.11 CN8.17 CN8.E1 CN8.E2 CN8.E3 CN8.E4 CN11.4 CN11.E1 CN11.E2 CN12.4(GND7) CN12.9(GND1) CN12.15(GND2) CN12.18(GND8) CN12.21(GND3) CN12.26(GND9) CN12.27(GND4) CN12.29(GND5) CN12.34(GND10) CN12.35(GND6) CN12.37(RSVD5) CN12.40(GND11) CN12.43(RSVD8) CN12.50(GND12) CN12.E1 CN12.E2 CN12.E3 CN13.3 CN13.E1 CN13.E2 CN14.3 CN14.16 CN14.17 CN14.19 CN14.E1 CN14.E2 CN15.4 CN15.E1 CN15.E2 CN15.E3 CN15.E4 CN16.5 CN16.8 CN16.11 CN16.14 CN16.17 CN16.20 CN16.E1 CN16.E2 CN17.1 CN17.4 CN17.E1 CN17.E2 CN18.4 CN18.7 CN18.10 CN18.13 CN18.16 CN18.19 CN18.E1 CN18.E2 CN19.1 CN19.E1 CN19.E2 CN20.E1 CN20.E2 CN22.1 CN22.4 CN22.E1 CN22.E2 CN24.1 CN24.4 CN24.7 CN24.8 CN24.9 CN24.10 CN24.E1 CN24.E2 CN26.1 CN26.4 CN26.7 CN26.8 CN26.9 CN26.10 CN26.E1 CN26.E2 CN27.4 CN27.E1 CN27.E2 CN27.E3 CN27.E4 CN28.4 CN28.E1 CN28.E2 CN28.E3 CN28.E4 CN30.E1 CN30.E2 CN30.E3 CN30.E4 CN30.M1(VSS1_MS) CN30.M10(VSS2_MS) CN30.S3(VSS1_SD) CN30.S6(VSS2_SD) CN34.2 CN34.4 CN34.E1 CN34.E2 CP1.2 CP4.2 CP5.2 CP6.2 CP7.2 CP9.2 CP11.2 CP12.2 CP13.2 CP14.2 CP18.2 CP19.2 CP20.2 CP25.2 CP26.2 CP50.2 D6.1(X1) D12.P D13.P D14.P D27.P D28.P D44.P D45.P D46.P D47.P D48.P D49.P FB11.1 FB32.1 J2.4(GND1) J2.7(GND_DRAIN) J2.E1(GND2) J2.E2(GND3) J3.4 J3.5 J3.E1 J3.E2 J5.E1 J5.E2 J13.1 J13.2 J13.5 MH1.1 MH2.1 MH3.1 MH4.1 MH5.1 MH6.1 MH7.1 MH8.1 MH9.1 MH10.1 Q1.2(S) Q2.2(S) Q3.2(S) Q5.2(GND) Q7.2(S) Q8.2(S) Q13.2(S) Q14.2(S) Q16.2(S) Q17.2(S) Q25.2(SOURCE) Q34.4 Q35.4 Q36.2(S) Q37.4 Q38.2(S) Q39.2(S) Q40.4 Q41.3(S2) Q41.4(S3) Q41.5(S4) Q42.3(D) Q43.2(S) Q44.2(SOURCE) Q45.2(S) Q46.2(S) Q47.2(S) Q48.2(S) Q49.2(S) Q50.2(S) Q51.2(S) Q52.2(S) Q53.2(S) Q54.2(S) Q55.2(S) Q56.2(S) Q57.2(S) Q58.2(S) Q59.2(S) Q61.2(S) Q63.2(S) Q67.2(S) Q68.2(S) Q70.2(SOURCE) Q71.2(S) Q72.2(S) Q73.2(S) Q74.2(S) Q75.2(S) Q76.2(S) Q77.2(S) Q78.2(S) Q79.2(S) Q80.2(S) Q81.2(S) Q82.2(S) Q83.2(S) Q84.2(S) Q85.2(S) Q86.2(S) Q87.3(S2) Q87.4(S3) Q87.5(S4) Q88.2(S) Q89.2(S) Q90.2(S) Q98.3(D) Q100.2(S) R1.1 R2.1 R3.2 R4.2 R5.2 R9.1 R10.2 R14.2 R15.1 R16.1 R18.1 R22.1 R23.2 R24.1 R25.2 R26.2 R32.1 R33.1 R35.1 R38.2 R40.2 R45.2 R46.1 R53.1 R55.2 R58.1 R60.1 R61.1 R64.2 R67.2 R78.2 R85.1 R86.2 R87.2 R88.2 R92.1 R93.1 R94.1 R99.1 R100.2 R115.1 R122.2 R123.2 R124.1 R126.1 R129.1 R131.1 R137.2 R159.1 R161.1 R163.2 R164.2 R178.2 R182.2 R189.1 R199.1 R209.1 R210.1 R213.1 R215.2 R219.2 R223.2 R239.2 R292.2 R311.2 R320.2 R330.2 R331.2 R343.1 R347.1 R352.1 R354.2 R356.1 R365.1 R370.1 R374.1 R379.1 R421.2 R422.2 R425.1 R426.2 R436.2 R438.1 R446.1 R447.1 R451.1 R464.2 R470.1 R475.1 R478.1 R481.1 R482.2 R485.1 R489.2 R491.2 R496.2 R499.1 R506.2 R509.2 R529.1 R538.2 R549.2 R550.2 R551.2 R552.1 R553.1 R554.2 R555.2 R574.1 R597.2 R601.1 R621.1 R626.1 R646.1 R659.2 R663.1 R687.2 R688.2 R690.1 R697.2 R698.1 R707.1 R709.1 R722.1 R726.1 R727.1 R735.1 R737.1 R740.2 R800.2 R802.1 R805.1 R883.1 R900.1 R904.1 R958.1 R960.1 R1114.1 SW1.1 SW1.2 SW1.5 SW1.6 SW2.2 SW2.4 SW4.2 SW4.6 U1.A3(VSS_A3_A3) U1.A5(VSS_A5_A5) U1.A6(VSS_A6_A6) U1.A11(VSS1) U1.A15(VSS2) U1.A19(VSS3) U1.A23(VSS4) U1.A27(VSS5) U1.A31(VSS6) U1.A35(VSS7) U1.A39(VSS8) U1.A43(VSS9) U1.A47(VSS10) U1.A49(VSS_A49_A49) U1.A51(VSS_A51_A51) U1.A52(VSS_A52_A52) U1.AA1(VSS11) U1.AA3(VSS15) U1.AA16(VSS12) U1.AA19(VSS13) U1.AA21(VSS14) U1.AA32(VSS16) U1.AA35(VSS17) U1.AA38(VSS18) U1.AA53(VSS19) U1.AB4(VSS21) U1.AB6(VSS28) U1.AB10(VSS20) U1.AB41(VSS22) U1.AB45(VSS23) U1.AB47(VSS24) U1.AB48(VSS25) U1.AB50(VSS26) U1.AB51(VSS27) U1.AC16(VSS29) U1.AC18(VSS30) U1.AC19(VSS31) U1.AC21(VSS32) U1.AC25(VSS33) U1.AC33(VSS34) U1.AC35(VSS35) U1.AC36(VSS36) U1.AC38(VSS37) U1.AD7(VSS44) U1.AD19(VSS38) U1.AD21(VSS39) U1.AD25(VSS40) U1.AD32(VSS41) U1.AD33(VSS42) U1.AD47(VSS43) U1.AE1(VSS45) U1.AE3(VSS49) U1.AE4(VSS50) U1.AE6(VSS60) U1.AE8(VSS61) U1.AE9(VSS62) U1.AE11(VSS46) U1.AE12(VSS47) U1.AE14(VSS48) U1.AE40(VSS51) U1.AE42(VSS52) U1.AE43(VSS53) U1.AE45(VSS54) U1.AE46(VSS55) U1.AE48(VSS56) U1.AE50(VSS57) U1.AE51(VSS58) U1.AE53(VSS59) U1.AF10(VSS63) U1.AF12(VSS64) U1.AF25(VSS65) U1.AF32(VSS66) U1.AF47(VSS67) U1.AG16(VSS68) U1.AG25(VSS69) U1.AG36(VSS70) U1.AG38(VSS71) U1.AH4(VSS72) U1.AH6(VSS110) U1.AH7(VSS75) U1.AH9(VSS76) U1.AH41(VSS73) U1.AH45(VSS74) U1.AH47(VSS106) U1.AH48(VSS107) U1.AH50(VSS108) U1.AH51(VSS109) U1.AJ1(VSS77) U1.AJ3(VSS83) U1.AJ16(VSS78) U1.AJ21(VSS79) U1.AJ25(VSS80) U1.AJ27(VSS81) U1.AJ29(VSS82) U1.AJ30(VSS84) U1.AJ32(VSS85) U1.AJ33(VSS86) U1.AJ35(VSS87) U1.AJ38(VSS88) U1.AJ53(VSS89) U1.AK10(VSS90) U1.AK14(VSS91) U1.AK16(VSS92) U1.AK33(VSS93) U1.AK41(VSS94) U1.AK44(VSS95) U1.AM7(VSS113) U1.AM12(VSS96) U1.AM19(VSS97) U1.AM24(VSS98) U1.AM25(VSS99) U1.AM29(VSS100) U1.AM33(VSS101) U1.AM35(VSS102) U1.AM36(VSS103) U1.AM40(VSS104) U1.AM44(VSS111) U1.AM51(VSS112) U1.AN1(VSS114) U1.AN3(VSS119) U1.AN5(VSS131) U1.AN6(VSS134) U1.AN8(VSS135) U1.AN9(VSS136) U1.AN11(VSS115) U1.AN12(VSS116) U1.AN14(VSS117) U1.AN16(VSSA_AN16) U1.AN22(VSS118) U1.AN33(VSS120) U1.AN35(VSS121) U1.AN36(VSS122) U1.AN38(VSS123) U1.AN40(VSS124) U1.AN42(VSS125) U1.AN43(VSS126) U1.AN45(VSS127) U1.AN46(VSS128) U1.AN48(VSS129) U1.AN49(VSS130) U1.AN51(VSS132) U1.AN53(VSS133) U1.AP40(VSS137) U1.AT4(VSS146) U1.AT12(VSS138) U1.AT16(VSS139) U1.AT19(VSS140) U1.AT24(VSS141) U1.AT27(VSS142) U1.AT30(VSS143) U1.AT35(VSS144) U1.AT38(VSS145) U1.AT47(VSS147) U1.AT52(VSS148) U1.AU1(VSS149) U1.AU3(VSS151) U1.AU24(VSS150) U1.AU30(VSS152) U1.AU38(VSS153) U1.AU51(VSS154) U1.AV7(VSS167) U1.AV12(VSS155) U1.AV13(VSS156) U1.AV14(VSS157) U1.AV18(VSS158) U1.AV19(VSS159) U1.AV24(VSS160) U1.AV27(VSS161) U1.AV30(VSS162) U1.AV35(VSS163) U1.AV38(VSS164) U1.AV47(VSS165) U1.AV51(VSS166) U1.AW3(VSS171) U1.AW13(VSS168) U1.AW19(VSS169) U1.AW27(VSS170) U1.AW35(VSS172) U1.AY3(VGA_IRTN) U1.AY4(VSS177) U1.AY9(VSS179) U1.AY10(VSS173) U1.AY22(VSS174) U1.AY32(VSS175) U1.AY36(VSS176) U1.AY50(VSS178) U1.B2(VSS_B2_B2) U1.B52(VSS_B52_B52) U1.B53(VSS_B53_B53) U1.BA14(VSS180) U1.BA19(VSS181) U1.BA22(VSS182) U1.BA27(VSS183) U1.BA32(VSS184) U1.BA35(VSS185) U1.BA40(VSS186) U1.BA53(VSS187) U1.BB19(VSS188) U1.BB27(VSS189) U1.BB35(VSS190) U1.BC20(VSS191) U1.BC22(VSS192) U1.BC26(VSS193) U1.BC28(VSS194) U1.BC32(VSS195) U1.BC34(VSS196) U1.BC42(VSS197) U1.BD19(VSS198) U1.BD24(VSS199) U1.BD27(VSS200) U1.BD30(VSS201) U1.BD35(VSS202) U1.BE1(VSS_BE1_BE1) U1.BE2(VSS204) U1.BE8(VSS206) U1.BE19(VSS203) U1.BE35(VSS205) U1.BE53(VSS_BE53_BE53) U1.BF4(VSS213) U1.BF12(VSS207) U1.BF16(VSS208) U1.BF24(VSS209) U1.BF30(VSS211) U1.BF36(VSS212) U1.BF38(VSS210) U1.BG1(VSS_BG1_BG1) U1.BG31(VSS214) U1.BG34(VSS215) U1.BG39(VSS216) U1.BG42(VSS217) U1.BG45(VSS218) U1.BG49(VSS219) U1.BG53(VSS_BG53_BG53) U1.BH1(VSS_BH1_BH1) U1.BH2(VSS_BH2_BH2) U1.BH52(VSS_BH52_BH52) U1.BH53(VSS_BH53_BH53) U1.BJ2(VSS_BJ2_BJ2) U1.BJ3(VSS_BJ3_BJ3) U1.BJ5(VSS_BJ5_BJ5) U1.BJ7(VSS230) U1.BJ11(VSS220) U1.BJ15(VSS221) U1.BJ19(VSS222) U1.BJ23(VSS223) U1.BJ27(VSS224) U1.BJ31(VSS225) U1.BJ35(VSS226) U1.BJ39(VSS227) U1.BJ43(VSS228) U1.BJ47(VSS229) U1.BJ49(VSS_BJ49_BJ49) U1.BJ51(VSS_BJ51_BJ51) U1.BJ52(VSS_BJ52_BJ52) U1.C1(VSS_C1_C1) U1.C14(VSS231) U1.C31(VSS232) U1.C34(VSS233) U1.C39(VSS234) U1.C42(VSS235) U1.C45(VSS236) U1.C49(VSS237) U1.C53(VSS_C53_C53) U1.D12(VSS238) U1.D16(VSS239) U1.D24(VSS240) U1.D30(VSS241) U1.D36(VSS242) U1.D38(VSS243) U1.E1(VSS_E1_E1) U1.E8(VSS246) U1.E19(VSS244) U1.E35(VSS245) U1.E53(VSS_E53_E53) U1.F2(VSS248) U1.F5(VSS253) U1.F7(VSS254) U1.F19(VSS247) U1.F24(VSS249) U1.F27(VSS250) U1.F30(VSS251) U1.F35(VSS252) U1.G10(VSS255) U1.G20(VSS256) U1.G22(VSS257) U1.G26(VSS258) U1.G28(VSS259) U1.G32(VSS260) U1.G34(VSS261) U1.G42(VSS262) U1.H19(VSS263) U1.H27(VSS264) U1.H35(VSS265) U1.J1(VSS266) U1.J16(VSS267) U1.J19(VSS268) U1.J22(VSS269) U1.J27(VSS270) U1.J32(VSS271) U1.J35(VSS272) U1.J40(VSS273) U1.J53(VSS274) U1.K4(VSS279) U1.K9(VSS281) U1.K14(VSS275) U1.K22(VSS276) U1.K32(VSS277) U1.K36(VSS278) U1.K50(VSS280) U1.L13(VSS282) U1.L19(VSS283) U1.L27(VSS284) U1.L35(VSS285) U1.M19(VSS286) U1.M26(VSS287) U1.M27(VSS288) U1.M28(VSS105) U1.M34(VSS289) U1.M35(VSS290) U1.M38(VSS291) U1.M47(VSS292) U1.M51(VSS293) U1.N1(VSS294) U1.N16(VSS295) U1.N38(VSS296) U1.N51(VSS297) U1.P4(VSS306) U1.P9(VSS309) U1.P13(VSS298) U1.P16(VSS299) U1.P19(VSS300) U1.P20(VSS301) U1.P24(VSS302) U1.P32(VSS303) U1.P35(VSS304) U1.P38(VSS305) U1.P47(VSS307) U1.P52(VSS308) U1.T40(VSS310) U1.U1(VSS311) U1.U3(VSS316) U1.U5(VSS326) U1.U6(VSS329) U1.U8(VSS330) U1.U9(VSS331) U1.U11(VSS312) U1.U12(VSS313) U1.U14(VSS314) U1.U16(USB_VSSA_U16) U1.U21(VSS315) U1.U30(VSS317) U1.U32(VSS318) U1.U40(VSS319) U1.U42(VSS320) U1.U43(VSS321) U1.U45(VSS322) U1.U46(VSS323) U1.U48(VSS324) U1.U49(VSS325) U1.U51(VSS327) U1.U53(VSS328) U1.V7(VSS340) U1.V12(VSS332) U1.V16(VSS333) U1.V19(VSS334) U1.V21(VSS335) U1.V35(VSS336) U1.V40(VSS337) U1.V44(VSS338) U1.V51(VSS339) U1.Y7(VSS349) U1.Y9(VSS350) U1.Y10(VSS341) U1.Y14(VSS342) U1.Y16(VSS343) U1.Y21(VSS344) U1.Y25(VSS345) U1.Y33(VSS346) U1.Y41(VSS347) U1.Y44(VSS348) U3.4(VSS) U5.5(GND) U5.E1 U6.6(GND) U7.5(GND) U8.5(GND) U8.E1 U9.2(GND) U10.3(GND) U10.17(GNDX) U10.18(GNDX_1) U10.28(GND1) U10.E1 U12.1(A0/E0) U12.2(A1/E1) U12.3(A2/E2) U12.4(GND) U13.1(A0/E0) U13.2(A1/E1) U13.3(A2/E2) U13.4(GND) U14.2(GND2) U14.5(GND5) U14.8(GND8) U14.11(GND11) U15.1(GND) U16.5(GND) U16.E1 U17.24(GND) U17.E1(EPAD) U19.2(GND) U20.5(GND) U20.E1 U21.2(GND) U22.2(GND) U23.4(DVSS) U23.E1 U24.3(GND) U25.2(GNDA) U25.15(GNDP) U25.E1 U26.6(GND) U27.6(GND) U28.1(VSS1) U28.27(VSS2) U28.49(VSS3) U28.75(AVSS) U28.91(VSS4) U29.3(GND) U30.4(GND) U31.2(GND) U32.3(GND) U33.3(GND) U34.3(GND) U36.3(GND) U37.3(GND) U38.3(GND) U39.3(GND) U40.3(GND) U41.2(GND) U42.15(GND) U42.E1 U43.4(VTTGND) U43.7(GND) U43.10(PGND) U43.E1 U44.5(GND) U44.E1 U45.5(GND) U45.E1 U46.5(GND) U46.E1 U47.7(GND) U47.8(PGND) U47.E1 U48.5(GND) U48.E1 U49.E1 U50.E1 U51.5(GND) U51.E1 U52.E1 U53.E1 U54.5(GND) U54.E1 U55.2(GND) U56.6(CCSN2) U56.8(CCSP3) U56.9(CCSN3) U56.42(PGNG) U56.E1 U57.6(GND) U57.E1 U58.3(GND) U59.2(GND) U60.5(GND) U60.E1 U63.3(GND) U65.4(GND) U68.5(GND) U68.E1 U69.5(GND) U69.E1 U70.2(GND) U71.3(GND) U73.2(GND) U74.4(GND) U75.4(GND) U75.E1 U76.2(GND) U77.15(GND) U79.4(-V) U83.15(GND) U84.2(GND) U95.E1 X1.2 X1.4 X3.2 X3.3 X4.2 X4.4 X6.2 X6.3 X7.2 X7.4 X8.2 X8.4
GND_EARTH: C271.2 C272.1 C337.1 C338.1 C460.1 C461.2 CN9.E1 CN9.E2 FB32.2
V1P0A_VR_PWRGD: C766.1 Q50.3(D) R466.1 R732.2 R734.2 U50.6(ENB)
V1P0S_EN: Q81.3(D) R458.2 R493.2 R645.2 U46.3(ON)
V1P0SX_PWRGD: R716.1 R724.2 U34.1(A)
V1P2A_VR_PWRGD: R484.2 R715.1 R734.1 U28.120(TMRI0/GPC4)
V1P2S_EN: Q83.3(D) R492.1 R560.1 U54.3(ON)
V1P05S_EN: Q73.3(D) R476.2 R503.2
V1P5S_VR_PWRGD: Q82.3(D) R490.2 U51.3(ON)
V1P05S_VR_PWRGD: R453.2 R472.1 R477.2 U49.5(POK)
V1P8A_VR_PWRGD: R479.2 R483.2 R714.1 R715.2 R733.1 U50.5(POK)
V1P35S_PWRGD: Q71.3(D) Q86.3(D) R247.1 R498.2 U52.6(ENB)
V3P3S_EN: Q45.3(D) Q84.3(D) R385.1 R556.2 R560.2 U68.3(ON)
V5_CORE: C467.2 C469.1 C479.2 R514.1 U56.43(V5DRV) U56.48(V5) U57.4(VDD)
VBAT: R290.2 R291.2 U28.3(VBAT)
VCC1_USB3.0: C310.2 C311.2 C312.1 F3.2 J2.1(VBUS) R363.2 U31.1(VOUT)
VCC_8625: C166.1 FB3.1 R169.2 R170.2 R171.2 R187.1 R188.1 U10.13(VDDIOX) U10.14(VDDIOX_1) U12.8(VCC) U13.8(VCC)
VCC_USB1: C316.2 C317.1 C319.2 CN15.1 F4.2 R369.2 U55.1(VOUT)
VCC_USB2: C322.2 C323.1 C335.2 CN28.1 F5.2 R373.2 U59.1(VOUT)
VCC_USB3: C327.2 C328.1 C333.2 CN27.1 F6.2 R372.2 U41.1(VOUT)
VCCAPWROK_AND: U38.4(Y) U40.1(A)
VDD10: C199.2 C200.1 C201.1 C202.1 C203.1 C204.1 C205.1 C206.1 C207.1 L4.2 R220.2 U17.3(AVDD10) U17.6(AVDD10(NC)) U17.9(AVDD10A(NC)) U17.13(DVDD10) U17.29(DVDD10A) U17.41(DVDD10(NC)) U17.45(AVDD10A)
VDD12: C169.1 C171.2 C172.2 FB2.2 L3.1 U10.19(VDD12)
VDD18: C706.2 U95.18(VDD18)
VDD33: C190.1 C191.1 C192.1 C193.1 C194.1 C195.1 C196.1 Q64.1(G) R206.1 R207.2 R211.2 R214.1 R226.1 U16.7(VOUT2) U16.8(VOUT1) U17.12(AVDD33(NC)) U17.27(DVDD33) U17.39(DVDD3) U17.42(AVDD33) U17.47(AVDD33A) U17.48(AVDD33B)
VDDIO_8625: C150.2 C164.2 FB16.2 R154.2 R155.2 R184.2 R185.2 R186.2 U10.38(VDDIO) U10.50(VDDIO_1)
VDDRX: C160.2 C161.2 C162.2 FB2.1 U10.6(VDDRX)
1P0A_ONOFF: Q43.1(G) U28.32(PWM6/SSCK/GPA6)
1P05_FB: C563.2 R473.2 R475.2 U49.4(FB)
1P8A_FB: C564.2 R480.2 R482.1 U50.4(FB)
3.3ASOC_ONOFF: U28.97(HSCK/GPH4/ID4) U73.3(EN/ENB)
3A5A_PWRGD: R390.1 R457.1 R675.2 R732.1 U42.23(PGOOD)
5A_ONOFF: Q42.1(G) Q98.1(G) R702.2
8625_PD#: C152.2 R155.1 U10.10(PD#)
8625_PWMO: R165.2 U10.12(PWMO)
8625_RST#: C151.2 R154.1 U10.9(RST#)
+V_ADP_IN: C585.2 C586.2 C587.2 C602.2 C604.1 CP19.1 FB23.1 FB24.1 FB25.1 FB34.2 FB35.2 Q65.1(S1) Q65.2(S2) Q65.3(S3) R348.2 R720.1 R744.2 R899.2 R903.2 R959.2
+V_DC: C298.1 C360.1 C361.1 C362.1 C363.2 C364.2 C365.1 C366.1 C367.1 C376.2 C382.1 C383.1 C384.1 C405.2 C406.1 C407.1 C443.1 C444.1 C450.1 C451.1 C452.1 C453.1 C454.1 C455.1 C456.1 C457.1 C458.1 C459.1 C485.1 C486.1 C487.1 C488.1 C489.1 C490.1 C491.1 C492.1 C493.1 C542.1 C543.1 C544.1 C545.1 C546.1 C547.1 C598.1 C599.2 C601.1 C603.1 C607.2 CP25.1 CP26.1 L31.1 Q34.1 Q34.2 Q35.1 Q35.2 Q37.1 Q37.2 Q40.1 Q40.2 Q41.2(D1) Q65.5(D1) Q65.6(D2) Q65.7(D3) Q65.8(D4) Q87.2(D1) R465.1 R527.1 R641.1 R642.1 R643.1 R681.1 R708.1 R720.2 R902.2 U25.16(VIN) U42.16(VIN)
+V_LED: C297.1 CN6.1 CP50.1 D38.N D41.N J5.5 J5.6 R351.1 R619.1
+VCORE: C38.2 C39.1 C40.1 C41.2 C42.2 C46.1 C47.1 C48.1 C462.1 C463.2 C464.2 C470.1 C471.1 C472.1 CP12.1 CP13.1 L14.2 R508.2 R515.1 R519.1 U1.AA27(CORE_VCC_S0IX_AA27) U1.AA29(CORE_VCC_S0IX_AA29) U1.AA30(CORE_VCC_S0IX_AA30) U1.AC27(CORE_VCC_S0IX_AC27) U1.AC29(CORE_VCC_S0IX_AC29) U1.AC30(CORE_VCC_S0IX_AC30) U1.AD27(CORE_VCC_S0IX_AD27) U1.AD29(CORE_VCC_S0IX_AD29) U1.AD30(CORE_VCC_S0IX_AD30) U1.AF27(CORE_VCC_S0IX_AF27) U1.AF29(CORE_VCC_S0IX_AF29) U1.AG27(CORE_VCC_S0IX_AG27) U1.AG29(CORE_VCC_S0IX_AG29) U1.AG30(CORE_VCC_S0IX_AG30) U1.P26(CORE_VCC_S0IX_P26) U1.P27(CORE_VCC_S0IX_P27) U1.U27(CORE_VCC_S0IX_U27) U1.U29(CORE_VCC_S0IX_U29) U1.V27(CORE_VCC_S0IX_V27) U1.V29(CORE_VCC_S0IX_V29) U1.V30(CORE_VCC_S0IX_V30) U1.Y27(CORE_VCC_S0IX_Y27) U1.Y29(CORE_VCC_S0IX_Y29) U1.Y30(CORE_VCC_S0IX_Y30) U56.5(CCSN1)
+VCORE_VREF: C449.2 C466.2 C474.1 R507.1 R533.2 R542.1 R543.1 R544.1 R545.1 R546.1 R547.1 R548.1 U56.14(VREF)
+VGFX: C32.2 C33.2 C34.2 C35.2 C36.2 C37.2 C43.2 C44.2 C45.2 C476.2 C477.1 C478.2 C481.1 C482.1 C483.1 CP14.1 CP18.1 CP20.1 L15.2 R530.2 R536.1 R539.1 U1.AA24(UNCORE_VNN_S3_AA24) U1.AC22(UNCORE_VNN_S3_AC22) U1.AC24(UNCORE_VNN_S3_AC24) U1.AD22(UNCORE_VNN_S3_AD22) U1.AD24(UNCORE_VNN_S3_AD24) U1.AF22(UNCORE_VNN_S3_AF22) U1.AF24(UNCORE_VNN_S3_AF24) U1.AG22(UNCORE_VNN_S3_AG22) U1.AG24(UNCORE_VNN_S3_AG24) U1.AJ22(UNCORE_VNN_S3_AJ22) U1.AJ24(UNCORE_VNN_S3_AJ24) U1.AK22(UNCORE_VNN_S3_AK22) U1.AK24(UNCORE_VNN_S3_AK24) U1.AK25(UNCORE_VNN_S3_AK25) U1.AK27(UNCORE_VNN_S3_AK27) U1.AK29(UNCORE_VNN_S3_AK29) U1.AK30(UNCORE_VNN_S3_AK30) U1.AK32(UNCORE_VNN_S3_AK32) U1.AM22(UNCORE_VNN_S3_AM22) U56.28(GCSN)
+VSDIO: R116.1 R117.1 U1.AN27(SD3_V1P8V3P3_S3_AN27)
+VSFR: C50.2 C89.1 C90.1 C91.1 C92.1 C93.1 C94.1 C95.1 C395.2 C559.1 R452.2 R644.2 R676.2 U1.AA25(UNCORE_V1P35_S0IX_F5_AA25) U1.AD36(DRAM_V1P35_S0IX_F1_AD36) U1.AF19(UNCORE_V1P35_S0IX_F6) U1.AG19(UNCORE_V1P35_S0IX_F1_AG19) U1.AG32(UNCORE_V1P35_S0IX_F2_AG32) U1.U36(UNCORE_V1P35_S0IX_F4_U36) U1.V36(UNCORE_V1P35_S0IX_F3_V36) U44.7(VOUT2) U44.8(VOUT1)
+VSM: C22.2 C23.2 C24.2 C25.2 C26.2 C27.2 C28.2 C29.2 C30.2 C31.2 C108.2 C109.2 C110.2 C111.2 C112.2 C113.2 C114.2 C115.2 C120.2 C121.2 C122.2 C123.2 C124.2 C125.2 C126.2 C127.2 C385.2 C391.1 C397.2 C399.2 C418.1 C419.1 C536.1 C556.1 C558.1 CN3.75(VDD1) CN3.76(VDD2) CN3.81(VDD3) CN3.82(VDD4) CN3.87(VDD5) CN3.88(VDD6) CN3.93(VDD7) CN3.94(VDD8) CN3.99(VDD9) CN3.100(VDD10) CN3.105(VDD11) CN3.106(VDD12) CN3.111(VDD13) CN3.112(VDD14) CN3.117(VDD15) CN3.118(VDD16) CN3.123(VDD17) CN3.124(VDD18) CP1.1 CP9.1 L8.2 R6.2 R7.1 R120.2 R125.2 R449.1 R576.2 U1.A48(DRAM_VDD_S4) U1.AD38(DRAM_VDD_S4_AD38) U1.AF38(DRAM_VDD_S4_AF38) U1.AK38(DRAM_VDD_S4_AK38) U1.AM38(DRAM_VDD_S4_AM38) U1.AV41(DRAM_VDD_S4_AV41) U1.AV42(DRAM_VDD_S4_AV42) U1.BB46(DRAM_VDD_S4_BB46) U1.BD49(DRAM_VDD_S4_BD49) U1.BD52(DRAM_VDD_S4_BD52) U1.BD53(DRAM_VDD_S4_BD53) U1.BF44(DRAM_VDD_S4_BF44) U1.BG51(DRAM_VDD_S4_BG51) U1.BJ48(DRAM_VDD_S4_BJ48) U1.C51(DRAM_VDD_S4_C51) U1.D44(DRAM_VDD_S4_D44) U1.F49(DRAM_VDD_S4_F49) U1.F52(DRAM_VDD_S4_F52) U1.F53(DRAM_VDD_S4_F53) U1.H46(DRAM_VDD_S4_H46) U1.M41(DRAM_VDD_S4_M41) U1.M42(DRAM_VDD_S4_M42) U1.V38(DRAM_VDD_S4_V38) U1.Y38(DRAM_VDD_S4_Y38) U43.2(VLDOIN) U43.9(VDDQSNS) U44.1(VIN1) U44.2(VIN2) U45.1(VIN1) U45.2(VIN2) U49.7(VIN1) U49.8(VIN2) U49.9(VIN3)
+VSM_VTT: C105.1 C116.2 C117.2 C118.2 C119.2 C387.1 CN3.203(VTT1) CN3.204(VTT2) R723.2 U43.1(VTTSNS) U43.3(VTT)
A_EARPHONE_SEL: J4.3 R251.1 R268.1
AC_DETECT: J13.3 R348.1
AC_PRESENT: Q3.1(G) R328.2
AC_VREF: C230.1 C232.2 U23.28(VREF)
ADP_IN#: D15.P R338.2 U28.71(ADC5/DCD1/GPI5)
ALL_S_PWRGD: R386.2 R679.1 U34.2(B)
ALL_SX_S_PWRGD: R679.2 U34.4(Y) U36.2(B) U38.1(A)
ALL_SYS_PWRGD: R8.1 U28.87(PS2CLK1/DTR0#/GPF2) U36.4(Y) U37.2(B)
ALW_DISCHARGE: Q49.1(G) Q50.1(G) Q52.1(G) Q55.1(G) Q56.1(G) Q57.1(G) Q58.1(G) Q59.1(G) Q85.3(D) R662.1 R663.2
AUD_MIC1_IN_L: R245.2 R246.1 R669.2
AUD_MIC1_IN_R: R242.2 R244.1 R668.2
AUD_MIC2_IN_L: C249.1 C250.1 CN21.2 R249.2
AUDIO_DVDD_IO: C256.2 R258.1 R260.1 U23.9(DVDD-IO)
AUDIO_POWER_ON: R237.1 R239.1 R248.2 U19.3(EN/ENB) U20.3(ON) U21.3(EN/ENB) U22.3(EN/ENB)
AUXN_LVDS: C524.1 U10.1(DAUXN)
AUXP_LVDS: C526.1 U10.2(DAUXP)
BIOS_BOOT_SELECT: R51.1 R53.2 U1.BA30(LPE_I2S2_FRM)
BL_ADJ: R153.1 R176.1 U28.25(PWM1/GPA1)
BLCTL_EC: R325.2 R330.1 R748.2 U63.2(B)
BT_ON: R278.1 R282.1 U28.30(PWM4/GPA4)
BUF_PLT_RST#: CN14.4 R84.1 R218.2 R312.2 R589.2 U6.10(B1) U36.1(A) U39.2(B) U58.2(B)
CAM_ON: R597.1 U28.78(DAC2/GPJ2/TACH0B) U84.3(EN/ENB)
CF_IMAX: R542.2 R549.1 U56.13(CF-IMAX)
CLK_LAN_OE#: Q64.2(S) R41.1 R634.1 U1.BG3(P\C\I\E\_\C\L\K\R\E\Q\_\0\)
CLK_PCIE_LAN_N: U1.AF6(PCIE_CLKN_00) U17.20(REFCLK_N)
CLK_PCIE_LAN_P: U1.AF4(PCIE_CLKP_00) U17.19(REFCLK_P)
CLK_PCIE_WLAN_N: CN12.11(REFCLK-) U1.AF9(PCIE_CLKN_11)
CLK_PCIE_WLAN_P: CN12.13(REFCLK+) U1.AF7(PCIE_CLKP_11)
CLK_WLAN_OE#: Q66.2(S) R39.1 R635.1 U1.BD7(P\C\I\E\_\C\L\K\R\E\Q\_\1\)
